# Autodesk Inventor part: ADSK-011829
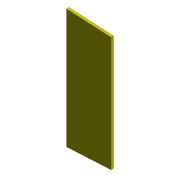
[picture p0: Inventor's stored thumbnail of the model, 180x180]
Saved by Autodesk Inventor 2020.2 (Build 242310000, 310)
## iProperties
Created: 1999-11
Part Number: ADSK-011829
Document SubType Name: Modeling
Designer: sspink
Material: Générique
Density: 1 g/cm^3
Appearance: Gelb
Mass: 24.3364 g
Surface Area: 174.341 cm^2
Volume: 24.3364 cm^3
Control State: 0
Checked Out: False
Last Check In By: sspink
Last Check In Date: 1999-12-22
Master: False
Shininess: 0.0
Length Units: 11269
Angle Units: 11279
Time Units: 11290
Mass Units: 11283
Length Display Precision: 3
Angle Display Precision: 2
Compacted: True
Dimensions: 149x3x55,6 mm
Mass: 0,024 kg
VLT_Material: Generisch
Density: 0.0
Volumn: 0.0
Area: 0.0
PropertySet Name: Model Information
Author: sspink
Revision Number: -
Title: ADSK-011829
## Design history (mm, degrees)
node "Solide1"
  node "Extrusion1" dims "d1" = 3, "d2" = 0
sketch "Sketch1"
  geometry: L1 (156.567, 56.011)-(156.567, -86.989); L2 (156.567, 56.011)-(101.005, 59.011); L3 (101.005, 59.011)-(101.005, -89.989) reference; L4 (101.005, -89.989)-(156.567, -86.989); L5 (101.005, -15.489)-(156.567, -15.489) reference
  constraints: 10 end point, 2 midpoint, 1 horizontal, 1 parallel, 1 perpendicular, 1 vertical
  dimensions: "d3" = 143 distance of L1.start L1.end; "d4" = 149 distance of L2.end L3.end; "d5" = 55.5625 distance between parallel lines of L1 L3
workplane "Work Plane1"
node "Corps solides"
node "Corps surfaciques"
other parameters: "d7" = 90 deg
